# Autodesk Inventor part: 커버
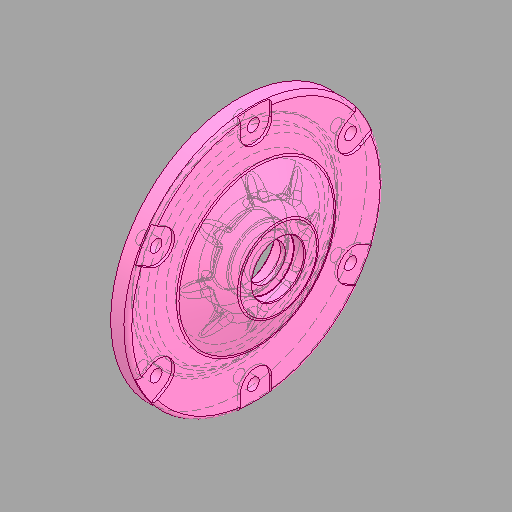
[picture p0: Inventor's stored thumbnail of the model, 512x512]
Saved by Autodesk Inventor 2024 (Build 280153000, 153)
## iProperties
Created: 2025-11
Part Number: 커버
Material: 알루미늄 6061
Document SubType Name: Modeling
Designer: Edu09
Density: 2.7 g/cm^3
Appearance: 기본값
Author: jhkim
Sending System: Autodesk Inventor 2026
Preprocessor: ST-DEVELOPER v20.1
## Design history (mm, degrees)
feature "솔리드1"
node "솔리드2"
